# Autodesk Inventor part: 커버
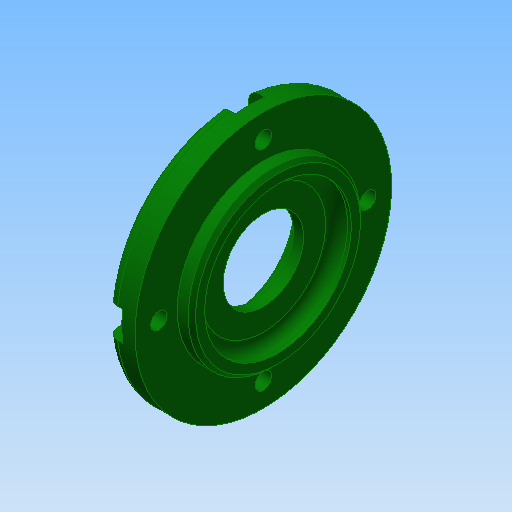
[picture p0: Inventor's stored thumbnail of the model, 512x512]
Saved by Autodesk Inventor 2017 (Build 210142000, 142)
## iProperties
Created: 2020-05
Part Number: 커버
Material: 알루미늄 6061
Document SubType Name: Modeling
Designer: mduedu
Density: 1 g/cm^3
Appearance: 진녹색
Author: mduedu
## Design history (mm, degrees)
sketch "스케치1"
  geometry: L1 (0, 0)-(8, 0); L2 (8, 0)-(8, 35); L3 (8, 35)-(0, 35); L4 (0, 35)-(0, 0); L5 (8, 0)-(12, 0); L6 (12, 0)-(12, 23.5); L7 (12, 23.5)-(8, 23.5); L8 (8, 23.5)-(8, 0)
  constraints: 16 end point, 4 parallel, 2 horizontal, 2 perpendicular
  dimensions: "d0" = 70 diameter of L3 L1; "d2" = 47 diameter of L7 L5; "d3" = 4 distance of L6.end L7.end; "d4" = 12 distance between parallel lines of L4 L6
revolve "회전1" sketch "스케치1" stored, may be unused: angle "d5" = 90 deg
hole "구멍1" diameter "d8" = 22; stored, may be unused: countersink angle "d12" = 90 deg, drill point angle "d14" = 118 deg; dims "d6" = 10, "d7" = 10, "d9" = 6, "d10" = 32, "d11" = 5.2, "d13" = 8
hole "구멍2" diameter "d17" = 40; stored, may be unused: countersink angle "d21" = 90 deg, drill point angle "d23" = 0 deg; dims "d15" = 10, "d16" = 10, "d18" = 6, "d19" = 32, "d20" = 5.2, "d22" = 4
fillet "모깎기1" dims "d24" = 3
fillet "모깎기2" dims "d25" = 3
fillet "모깎기3" dims "d26" = 0.3
chamfer "모따기1" distance "d27" = 0.5; stored, may be unused: second distance "d28" = 2, angle "d29" = 30 deg
chamfer "모따기2" distance "d30" = 1; stored, may be unused: second distance "d31" = 2, angle "d32" = 30 deg
sketch "스케치2" dims "d33" = 57
  geometry: L1 (-4, 28.5)-(4, 28.5); L2 (4, 28.5)-(4, 38.5); L3 (4, 38.5)-(-4, 38.5); L4 (-4, 38.5)-(-4, 28.5); 4 further points
  constraints: 8 end point, 2 horizontal alignment, 2 midpoint, 2 parallel, 2 vertical alignment, 1 coincident, 1 horizontal, 1 perpendicular, 6 other
  dimensions: "d34" = 8 distance between parallel lines of L2 L4; "d35" = 10 distance of point (0, 28.5) point (0, 38.5)
extrude "돌출1" cut sketch "스케치2" distance "d36" = 4.4; taper "d37" = 0 deg
sketch "스케치3"
  geometry: A1 r 4 centre (0, 28.5) between (-4, 28.5) and (4, 28.5) reference; 2 further points
  constraints: 1 coincident
hole "구멍3" sketch "스케치3" at (0, 28.5) diameter "d38" = 4.5; stored, may be unused: countersink angle "d42" = 90 deg, drill point angle "d44" = 0 deg; dims "d39" = 6, "d40" = 32, "d41" = 5.2, "d43" = 4
node "솔리드1"
pattern_circular "원형 패턴1" dims angle "d46" = 360 deg
